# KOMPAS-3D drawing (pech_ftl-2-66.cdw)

Referenced files: Печь ФТЛ-2-66.cdw
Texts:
  ОУП-02068108-260601-96-2010
  Печь ФТЛ-2-66
  Игорь
  Саранов И.А.
  Рязанов А.Н.
  УП-02068108-260601-2010-
Dimensions and other numbers on the sheet: 4295; 740; 3770; 890; 400; 5840; 1265; 3030; 1; 2; 3; 4; 5; 8; 7; 6; 0; 9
